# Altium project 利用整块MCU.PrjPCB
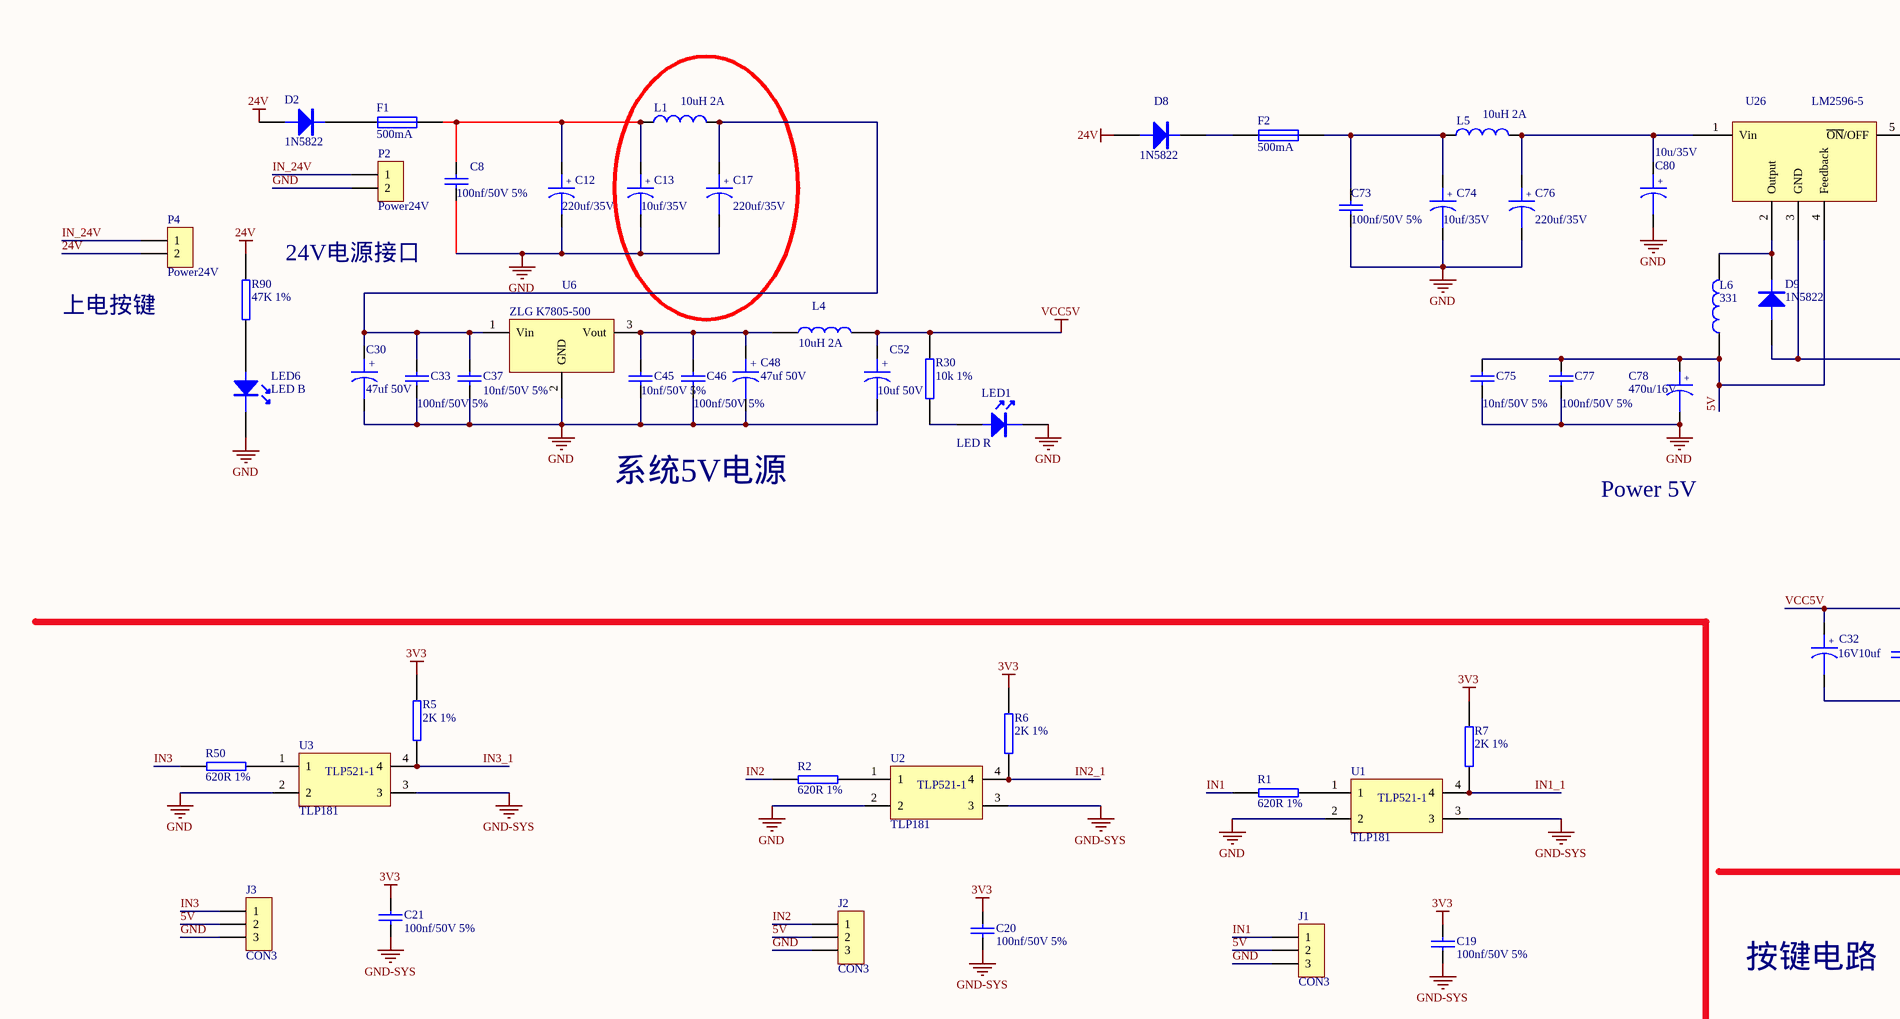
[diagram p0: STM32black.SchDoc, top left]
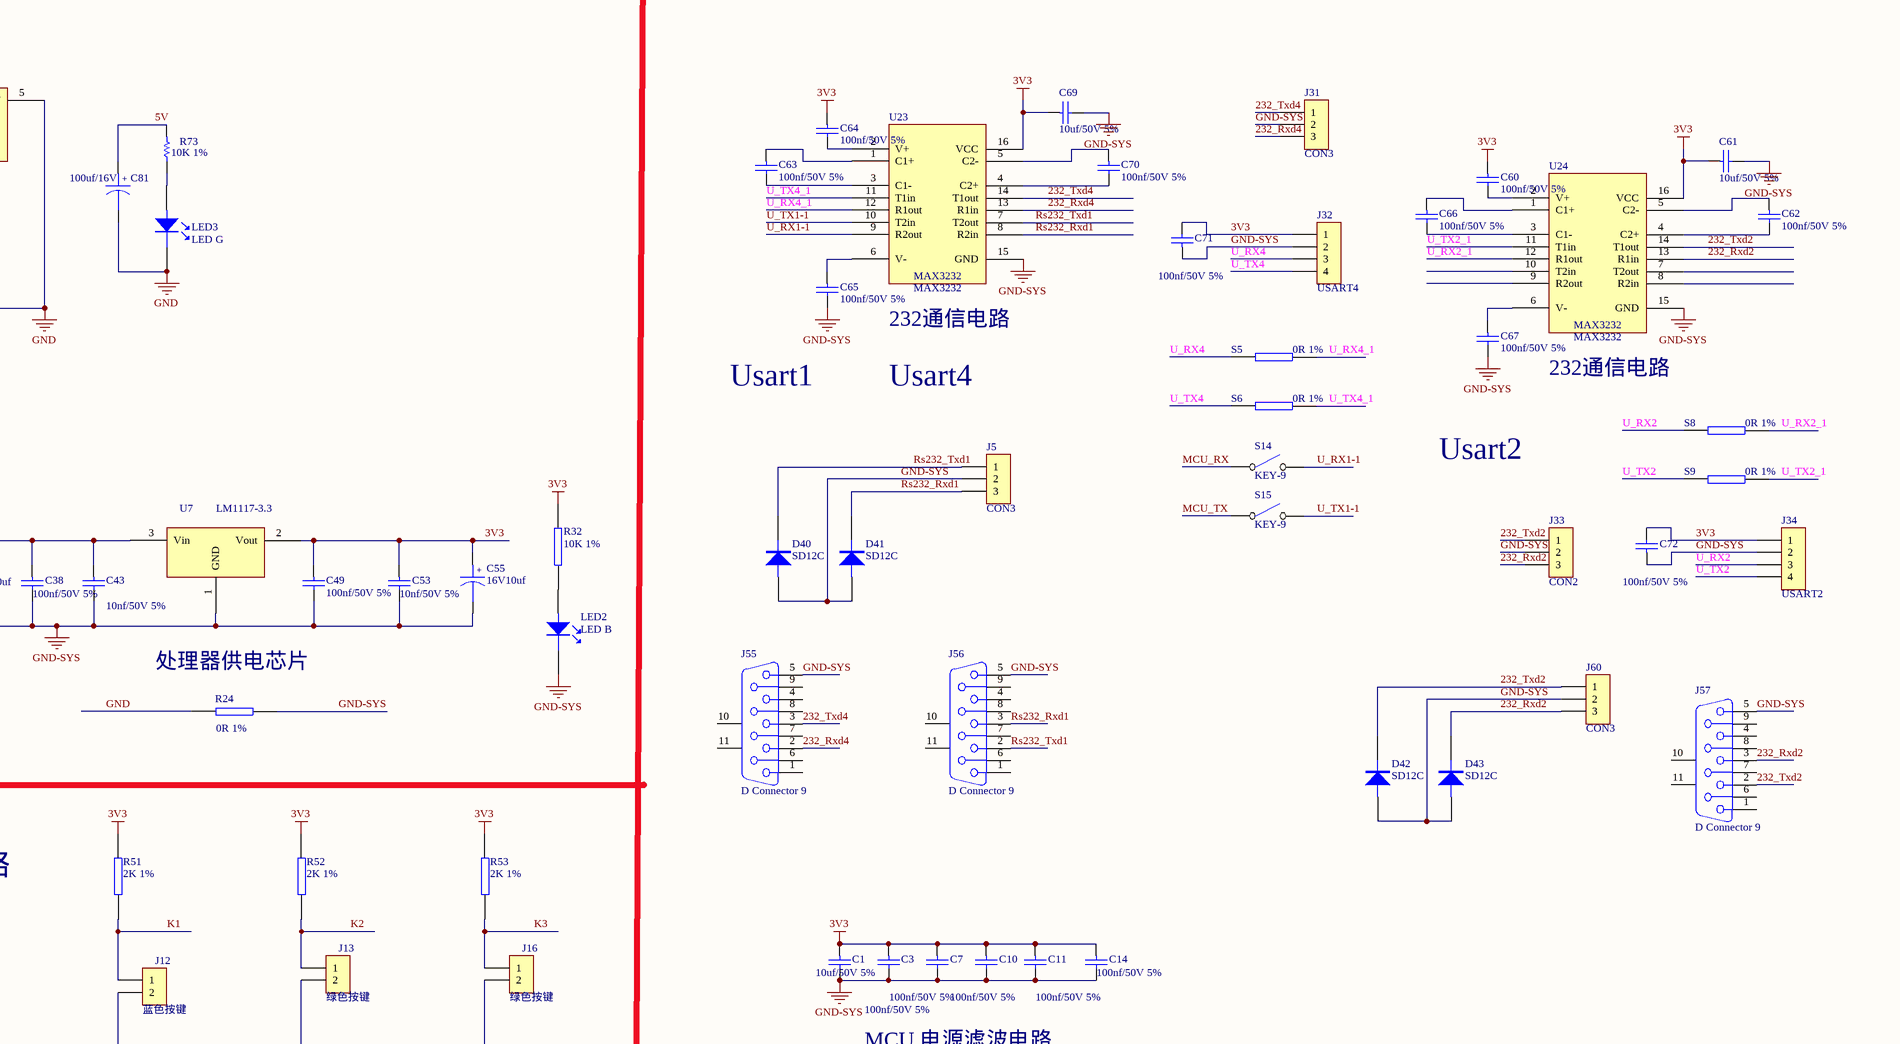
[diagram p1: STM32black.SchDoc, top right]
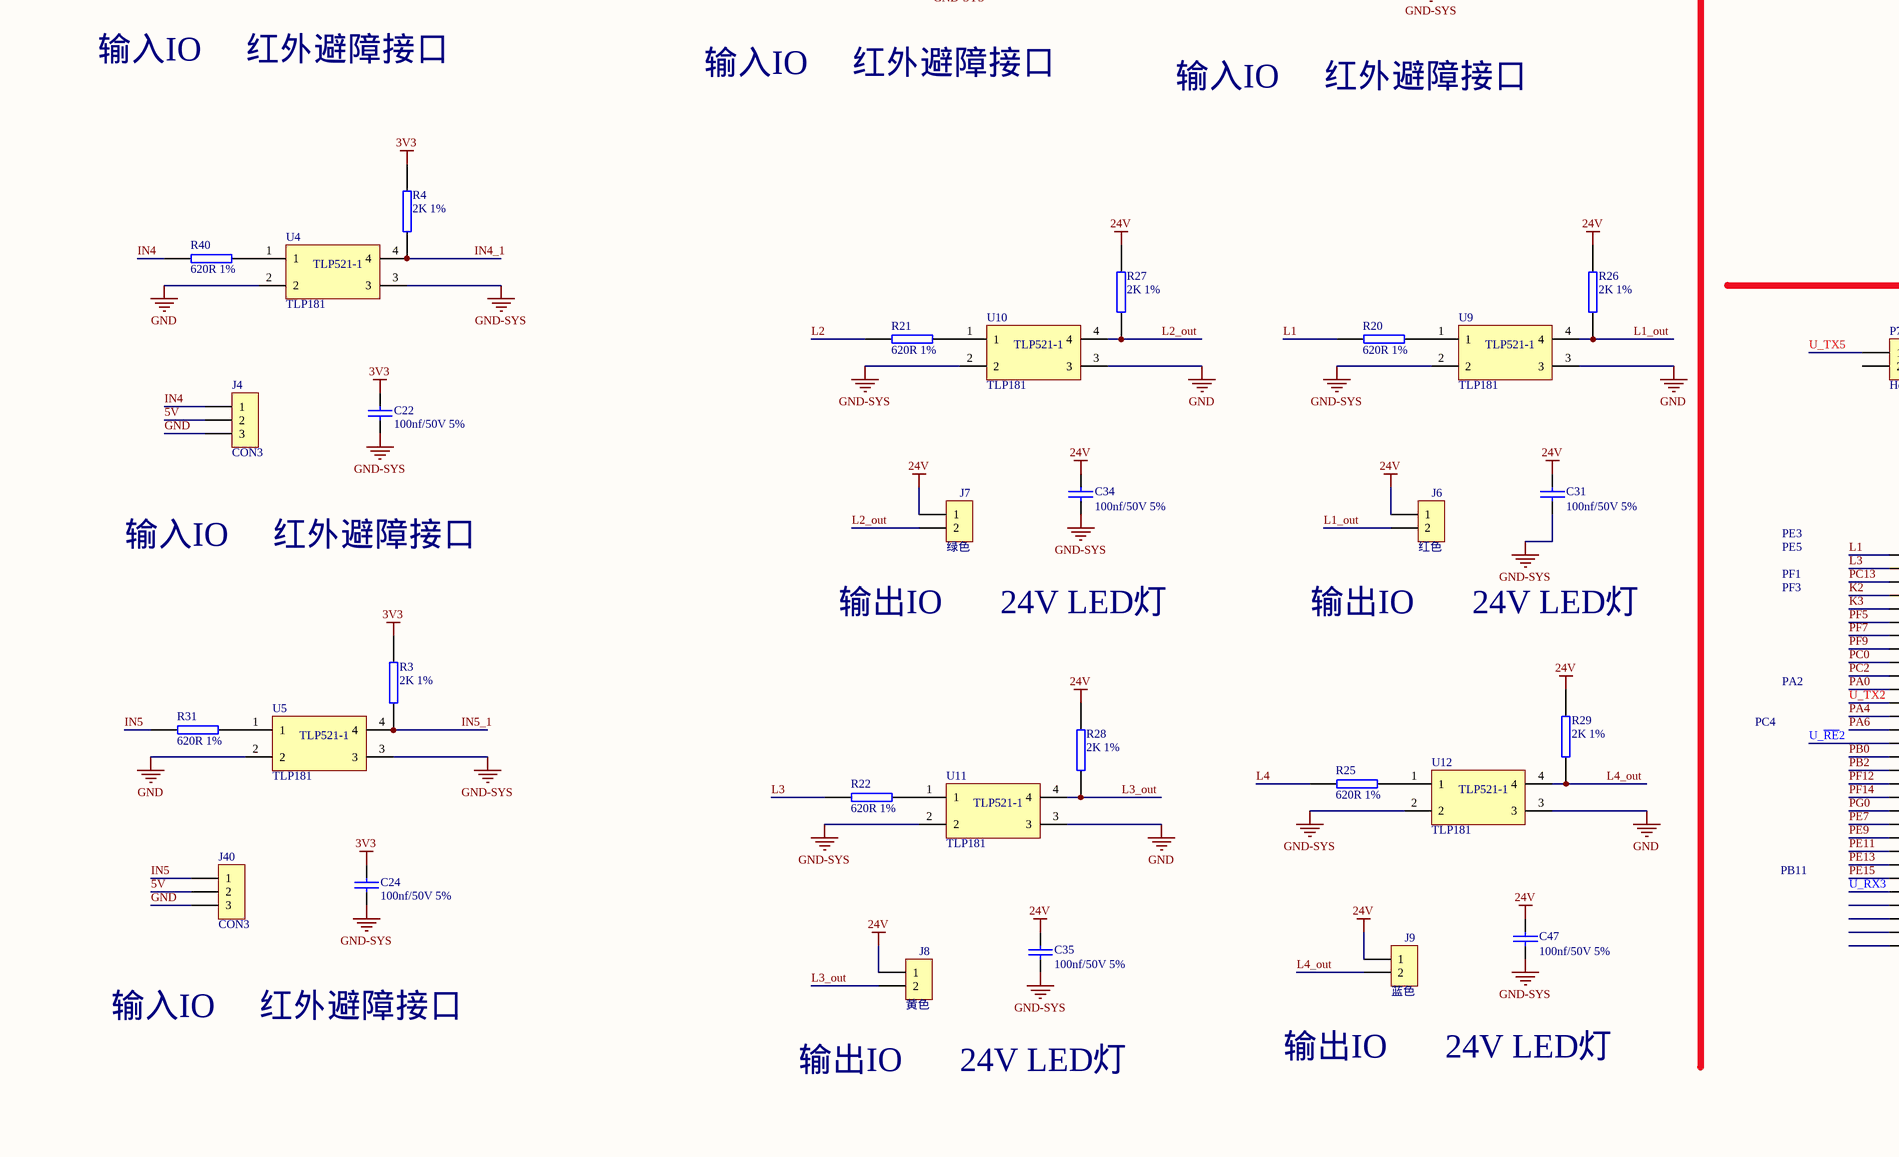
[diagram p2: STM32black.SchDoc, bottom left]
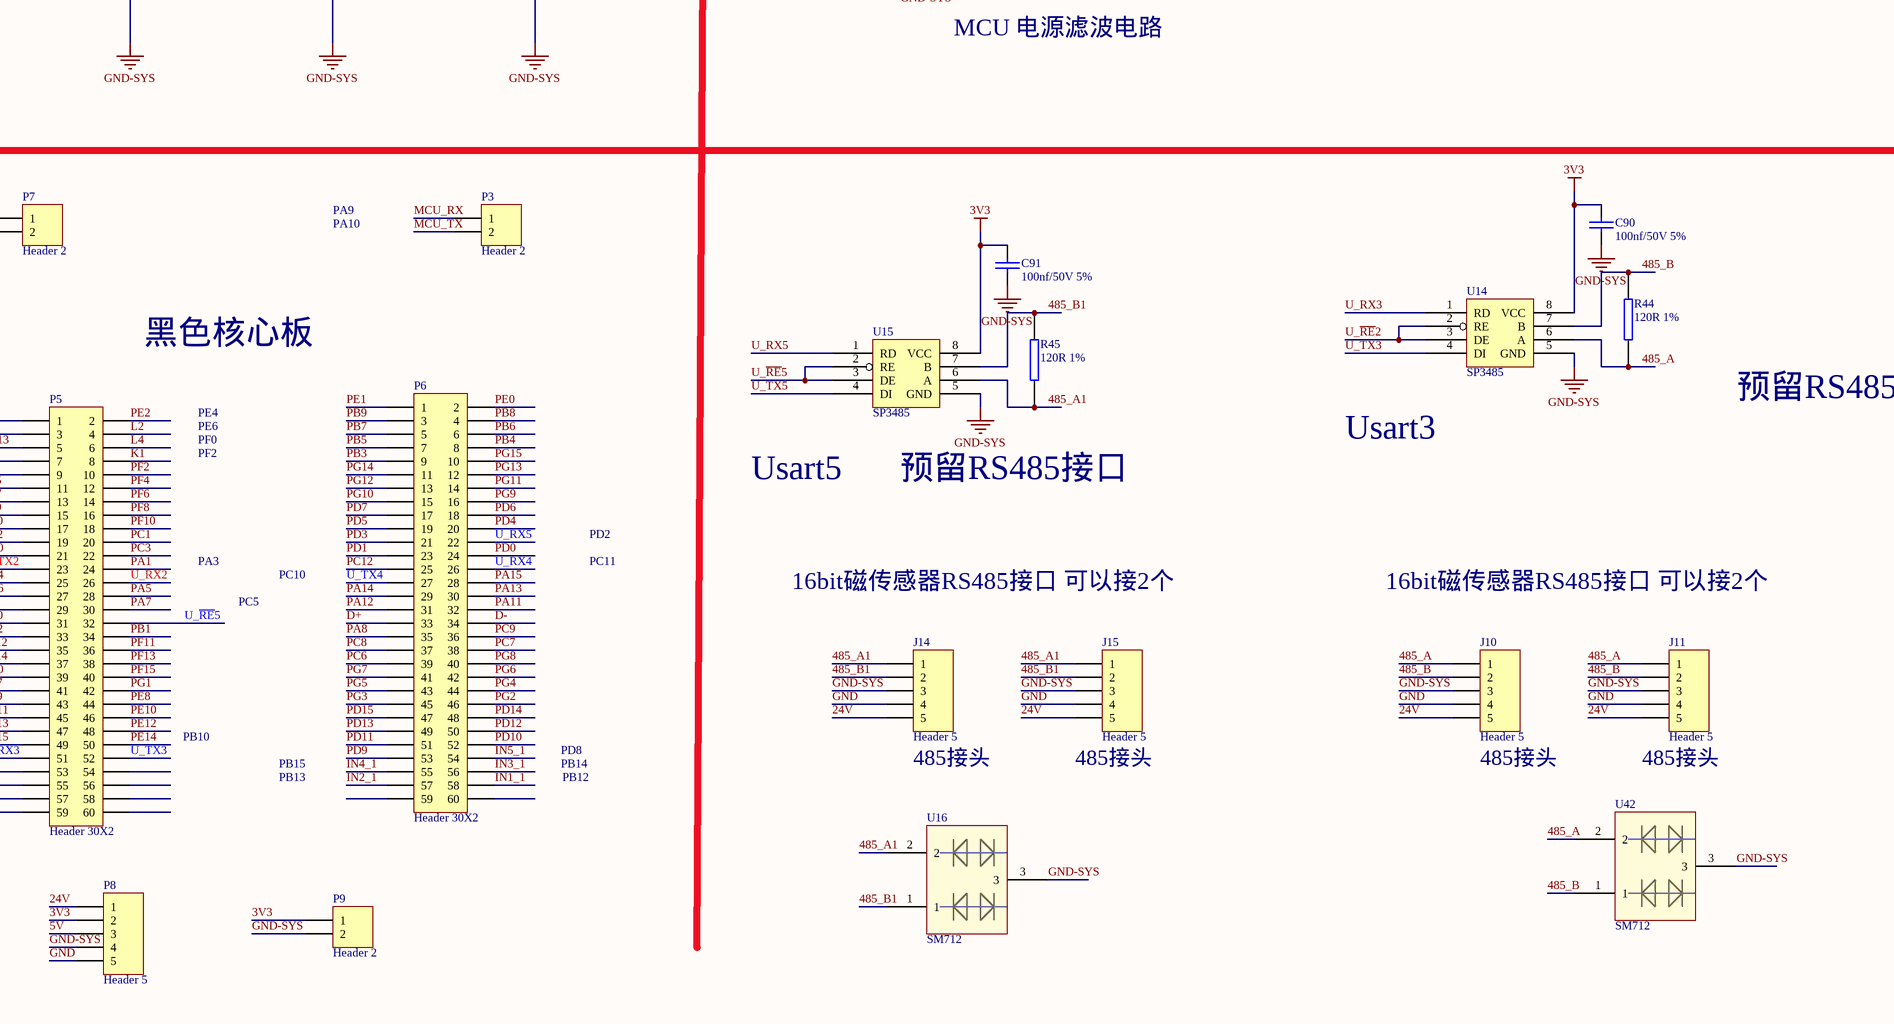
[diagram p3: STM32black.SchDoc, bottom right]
1 sheet, 156 parts. Net scope: global (net labels, ports and power ports of the same name join across sheets).
Board file: 利用整块MCU的投机取巧的PCB板.PcbDoc

## Sheet STM32black.SchDoc
size 762 x 457 mm; SheetNumber: 0; SheetTotal: 0

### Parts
C1  10uf/50V 5%  [0603]
C3  100nf/50V 5%  [0603]
C7  100nf/50V 5%  [0805C]
C8  100nf/50V 5%  [0805C]
C10  100nf/50V 5%  [0805C]
C11  100nf/50V 5%  [0805C]
C12  220uf/35V  [C10-35V330uf]
C13  10uf/35V  [C6.5-35V47uf]
C14  100nf/50V 5%  [0805C]
C17  220uf/35V  [C6.5-35V47uf]
C19  100nf/50V 5%  [0805C]
C20  100nf/50V 5%  [0805C]
C21  100nf/50V 5%  [0805C]
C22  100nf/50V 5%  [0805C]
C24  100nf/50V 5%  [0805C]
C30  47uf 50V  [C6.5-35V47uf]
C31  100nf/50V 5%  [0805C]
C32  16V10uf  [1206-2]
C33  100nf/50V 5%  [0805C]
C34  100nf/50V 5%  [0805C]
C35  100nf/50V 5%  [0805C]
C37  10nf/50V 5%  [0805C]
C38  100nf/50V 5%  [0805C]
C43  10nf/50V 5%  [0805C]
C45  10nf/50V 5%  [0805C]
C46  100nf/50V 5%  [0805C]
C47  100nf/50V 5%  [0805C]
C48  47uf 50V  [C6.5-35V47uf]
C49  100nf/50V 5%  [0805C]
C52  10uf 50V  [C6.5-35V47uf]
C53  10nf/50V 5%  [0805C]
C55  16V10uf  [1206-2]
C60  100nf/50V 5%  [0805C]
C61  10uf/50V 5%  [0805C]
C62  100nf/50V 5%  [0805C]
C63  100nf/50V 5%  [0805C]
C64  100nf/50V 5%  [0805C]
C65  100nf/50V 5%  [0805C]
C66  100nf/50V 5%  [0805C]
C67  100nf/50V 5%  [0805C]
C69  10uf/50V 5%  [0805C]
C70  100nf/50V 5%  [0805C]
C71  100nf/50V 5%  [0805C]
C72  100nf/50V 5%  [0805C]
C73  100nf/50V 5%  [0805C]
C74  10uf/35V  [C6.5-35V47uf]
C75  10nf/50V 5%  [0805C]
C76  220uf/35V  [C6.5-35V47uf]
C77  100nf/50V 5%  [0805C]
C78  470u/16V  [C10-35V330uf]
C80  10u/35V  [C6.5-35V47uf]
C81  100uf/16V  [C6.5-35V47uf]
C90  100nf/50V 5%  [0805C]
C91  100nf/50V 5%  [0805C]
D2  1N5822  [SS34]
D8  1N5822  [SS34]
D9  1N5822  [SS34]
D40  SD12C  [SD12C]
D41  SD12C  [SD12C]
D42  SD12C  [SD12C]
D43  SD12C  [SD12C]
F1  500mA  [1812]
F2  500mA  [1812]
J1  CON3  [CON-3P-3.81]
J2  CON3  [CON-3P-3.81]
J3  CON3  [CON-3P-3.81]
J4  CON3  [CON-3P-3.81]
J5  CON3  [CON-3P-3.81]
J6  红色  [CON-2P-3.81]
J7  绿色  [CON-2P-3.81]
J8  黄色  [CON-2P-3.81]
J9  蓝色  [CON-2P-3.81]
J10  Header 5  [CON-5P-3.81]
J11  Header 5  [CON-5P-3.81]
J12  蓝色按键  [CON-2P-3.81]
J13  绿色按键  [CON-2P-3.81]
J14  Header 5  [CON-5P-3.81]
J15  Header 5  [CON-5P-3.81]
J16  绿色按键  [CON-2P-3.81]
J31  CON3  [CON-3P-3.81]
J32  USART4  [SIP4]
J33  CON2  [CON-3P-3.81]
J34  USART2  [SIP4]
J40  CON3  [CON-3P-3.81]
J55  D Connector 9  [DSUB1.385-2H9]
J56  D Connector 9  [DSUB1.385-2H9]
J57  D Connector 9  [DSUB1.385-2H9]
J60  CON3  [CON-3P-3.81]
L1  value 10uH 2A  [LC-8.2]  (hidden comment: Inductor)
L4  10uH 2A  [LC-8.2]
L5  value 10uH 2A  [LC-8.2]  (hidden comment: Inductor)
L6  331  [LC-10]
LED1  LED R  [0805D]
LED2  LED B  [0805D]
LED3  LED G  [0805D]
LED6  LED B  [0805D]
P2  Power24V  [CON-2P-3.81]
P3  Header 2  [HDR1X2]
P4  Power24V  [CON-2P-3.81]
P5  Header 30X2  [HDR2X30]
P6  Header 30X2  [HDR2X30]
P7  Header 2  [HDR1X2]
P8  Header 5  [HDR1X5]
P9  Header 2  [HDR1X2]
R1  620R 1%  [0805R]
R2  620R 1%  [0805R]
R3  2K 1%  [0805R]
R4  2K 1%  [0805R]
R5  2K 1%  [0805R]
R6  2K 1%  [0805R]
R7  2K 1%  [0805R]
R20  620R 1%  [0805R]
R21  620R 1%  [0805R]
R22  620R 1%  [0805R]
R24  0R 1%  [0805R]
R25  620R 1%  [0805R]
R26  2K 1%  [0805R]
R27  2K 1%  [0805R]
R28  2K 1%  [0805R]
R29  2K 1%  [0805R]
R30  10k 1%  [0805R]
R31  620R 1%  [0805R]
R32  10K 1%  [0805R]
R40  620R 1%  [0805R]
R44  120R 1%  [0805R]
R45  120R 1%  [0805R]
R50  620R 1%  [0805R]
R51  2K 1%  [0805R]
R52  2K 1%  [0805R]
R53  2K 1%  [0805R]
R73  10K 1%  [0805R]
R90  47K 1%  [0805R]
S5  0R 1%  [0805R]
S6  0R 1%  [0805R]
S8  0R 1%  [0805R]
S9  0R 1%  [0805R]
S14  KEY-9  [SIP2]
S15  KEY-9  [SIP2]
U1  TLP181  [TLP-181]
U2  TLP181  [TLP-181]
U3  TLP181  [TLP-181]
U4  TLP181  [TLP-181]
U5  TLP181  [TLP-181]
U6  ZLG K7805-500  [TO-220]
U7  LM1117-3.3  [SOT-223]
U9  TLP181  [TLP-181]
U10  TLP181  [TLP-181]
U11  TLP181  [TLP-181]
U12  TLP181  [TLP-181]
U14  SP3485  [SO-8]
U15  SP3485  [SO-8]
U16  SM712  [SM712]
U23  MAX3232  [SO-16]
U24  MAX3232  [SO-16]
U26  LM2596-5  [TO-263-5]
U42  SM712  [SM712]

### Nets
3V3: C1.1 C3.1 C7.1 C10.1 C11.1 C14.1 C19.2 C20.2 C21.2 C22.2 C24.2 C49.1 C53.1 C55.1 C60.1 C61.1 C64.1 C69.1 C71.2 C72.2 C90.2 C91.2 J32.1 J34.1 P8.2 P9.1 R3.2 R4.2 R5.2 R6.2 R7.2 R32.2 R51.1 R52.1 R53.1 U7.2(Vout) U14.8(VCC) U15.8(VCC) U23.16(VCC) U24.16(VCC)
24V: C31.2 C34.2 C35.2 C47.2 D2.1(A) D8.1(A) J6.1 J7.1 J8.1 J9.1 J10.5 J11.5 J14.5 J15.5 P4.2 P8.1 R26.1 R27.1 R28.1 R29.1 R90.2
GND: C8.2 C12.2 C13.2 C17.2 C30.2 C33.2 C37.2 C45.2 C46.2 C48.2 C52.2 C73.2 C74.2 C75.2 C76.2 C77.2 C78.2 C80.2 C81.2 D9.1(A) J1.3 J2.3 J3.3 J4.3 J10.4 J11.4 J14.4 J15.4 J40.3 LED1.2 LED3.2 LED6.2 P2.2 P8.5 R24.1 U1.2 U2.2 U3.2 U4.2 U5.2 U6.2(GND) U9.3 U10.3 U11.3 U12.3 U26.3(GND) U26.5(~{ON}/OFF)
GND-SYS: C1.2 C3.2 C7.2 C10.2 C11.2 C14.2 C19.1 C20.1 C21.1 C22.1 C24.1 C31.1 C32.2 C34.1 C35.1 C38.2 C43.2 C47.1 C49.2 C53.2 C55.2 C61.2 C65.2 C67.2 C69.2 C71.1 C72.1 C90.1 C91.1 D40.1(A) D41.1(A) D42.1(A) D43.1(A) J5.2 J10.3 J11.3 J12.2 J13.2 J14.3 J15.3 J16.2 J31.2 J32.2 J33.2 J34.2 J55.5 J56.5 J57.5 J60.2 LED2.2 P8.4 P9.2 R24.2 U1.3 U2.3 U3.3 U4.3 U5.3 U7.1(GND) U9.2 U10.2 U11.2 U12.2 U14.5(GND) U15.5(GND) U16.3 U23.15(GND) U24.15(GND) U42.3
VCC5V: C32.1 C38.1 C43.1 C52.1 L4.2 R30.2 U7.3(Vin)
5V: C75.1 C77.1 C78.1 C81.1 J1.2 J2.2 J3.2 J4.2 J40.2 L6.1 P8.3 R73.2 U26.4(Feedback)
232_Rxd2: D43.2(K) J33.3 J57.3 J60.3 U24.13(R1in)
232_Rxd4: J31.3 J55.2 U23.13(R1in)
232_Txd2: D42.2(K) J33.1 J57.2 J60.1 U24.14(T1out)
232_Txd4: J31.1 J55.3 U23.14(T1out)
485_A: J10.1 J11.1 R44.2 U14.6(A) U42.2
485_A1: J14.1 J15.1 R45.2 U15.6(A) U16.2
485_B: J10.2 J11.2 R44.1 U14.7(B) U42.1
485_B1: J14.2 J15.2 R45.1 U15.7(B) U16.1
D+: P6.33
D-: P6.34
IN1: J1.1 R1.2
IN1_1: P6.58 R7.1 U1.4
IN2: J2.1 R2.2
IN2_1: P6.57 R6.1 U2.4
IN3: J3.1 R50.2
IN3_1: P6.56 R5.1 U3.4
IN4: J4.1 R40.2
IN4_1: P6.55 R4.1 U4.4
IN5: J40.1 R31.2
IN5_1: P6.54 R3.1 U5.4
IN_24V: P2.1 P4.1
K1: J12.1 P5.8 R51.2
K2: J13.1 P5.7 R52.2
K3: J16.1 P5.9 R53.2
L1: P5.1 R20.2
L1_out: J6.2 R26.2 U9.4
L2: P5.4 R21.2
L2_out: J7.2 R27.2 U10.4
L3: P5.3 R22.2
L3_out: J8.2 R28.2 U11.4
L4: P5.6 R25.2
L4_out: J9.2 R29.2 U12.4
MCU_RX: P3.1 S14.1(COMMON)
MCU_TX: P3.2 S15.1(COMMON)
PA0: P5.21
PA1: P5.24
PA4: P5.25
PA5: P5.28
PA6: P5.27
PA7: P5.30
PA8: P6.35
PA11: P6.32
PA12: P6.31
PA13: P6.30
PA14: P6.29
PA15: P6.28
PB0: P5.31
PB1: P5.34
PB2: P5.33
PB3: P6.9
PB4: P6.8
PB5: P6.7
PB6: P6.6
PB7: P6.5
PB8: P6.4
PB9: P6.3
PC0: P5.17
PC1: P5.20
PC2: P5.19
PC3: P5.22
PC6: P6.39
PC7: P6.38
PC8: P6.37
PC9: P6.36
PC12: P6.25
PC13: P5.5
PD0: P6.24
PD1: P6.23
PD3: P6.21
PD4: P6.20
PD5: P6.19
PD6: P6.18
PD7: P6.17
PD9: P6.53
PD10: P6.52
PD11: P6.51
PD12: P6.50
PD13: P6.49
PD14: P6.48
PD15: P6.47
PE0: P6.2
PE1: P6.1
PE2: P5.2
PE7: P5.41
PE8: P5.44
PE9: P5.43
PE10: P5.46
PE11: P5.45
PE12: P5.48
PE13: P5.47
PE14: P5.50
PE15: P5.49
PF2: P5.10
PF4: P5.12
PF5: P5.11
PF6: P5.14
PF7: P5.13
PF8: P5.16
PF9: P5.15
PF10: P5.18
PF11: P5.36
PF12: P5.35
PF13: P5.38
PF14: P5.37
PF15: P5.40
PG0: P5.39
PG1: P5.42
PG2: P6.46
PG3: P6.45
PG4: P6.44
PG5: P6.43
PG6: P6.42
PG7: P6.41
PG8: P6.40
PG9: P6.16
PG10: P6.15
PG11: P6.14
PG12: P6.13
PG13: P6.12
PG14: P6.11
PG15: P6.10
Rs232_Rxd1: D41.2(K) J5.3 J56.3 U23.8(R2in)
Rs232_Txd1: D40.2(K) J5.1 J56.2 U23.7(T2out)
U_~{RE}2: P5.29 U14.2(RE) U14.3(DE)
U_~{RE}5: P5.32 U15.2(RE) U15.3(DE)
U_RX1-1: S14.2(NO) U23.9(R2out)
U_RX2: J34.3 P5.26 S8.1
U_RX2_1: S8.2 U24.12(R1out)
U_RX3: P5.51 U14.1(RD)
U_RX4: J32.3 P6.26 S5.1
U_RX4_1: S5.2 U23.12(R1out)
U_RX5: P6.22 U15.1(RD)
U_TX1-1: S15.2(NO) U23.10(T2in)
U_TX2: J34.4 P5.23 S9.1
U_TX2_1: S9.2 U24.11(T1in)
U_TX3: P5.52 U14.4(DI)
U_TX4: J32.4 P6.27 S6.1
U_TX4_1: S6.2 U23.11(T1in)
U_TX5: P7.1 U15.4(DI)
NetC8_1: C8.1 C12.1 C13.1 F1.2 L1.1
NetC17_1: C17.1 C30.1 C33.1 C37.1 L1.2 U6.1(Vin)
NetC45_1: C45.1 C46.1 C48.1 L4.1 U6.3(Vout)
NetC60_2: C60.2 U24.2(V+)
NetC62_1: C62.1 U24.5(C2-)
NetC62_2: C62.2 U24.4(C2+)
NetC63_1: C63.1 U23.1(C1+)
NetC63_2: C63.2 U23.3(C1-)
NetC64_2: C64.2 U23.2(V+)
NetC65_1: C65.1 U23.6(V-)
NetC66_1: C66.1 U24.1(C1+)
NetC66_2: C66.2 U24.3(C1-)
NetC67_1: C67.1 U24.6(V-)
NetC70_1: C70.1 U23.5(C2-)
NetC70_2: C70.2 U23.4(C2+)
NetC73_1: C73.1 C74.1 F2.2 L5.1
NetC76_1: C76.1 C80.1 L5.2 U26.1(Vin)
NetD2_2: D2.2(K) F1.1
NetD8_2: D8.2(K) F2.1
NetD9_2: D9.2(K) L6.2 U26.2(Output)
NetLED1_1: LED1.1 R30.1
NetLED2_1: LED2.1 R32.1
NetLED3_1: LED3.1 R73.1
NetLED6_1: LED6.1 R90.1
NetR1_1: R1.1 U1.1
NetR2_1: R2.1 U2.1
NetR20_1: R20.1 U9.1
NetR21_1: R21.1 U10.1
NetR22_1: R22.1 U11.1
NetR25_1: R25.1 U12.1
NetR31_1: R31.1 U5.1
NetR40_1: R40.1 U4.1
NetR50_1: R50.1 U3.1

Not connected (* = marked no-connect by the designer): J55 1 4 6 7 8 9 10(MH1) 11(MH2); J56 1 4 6 7 8 9 10(MH1) 11(MH2); J57 1 4 6 7 8 9 10(MH1) 11(MH2); P5 53 54 55 56 57 58 59 60; P6 59 60; P7 2; U24 7(T2out) 8(R2in) 9(R2out) 10(T2in)

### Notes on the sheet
- 上电按键
- 24V电源接口
- 232通信电路
- Usart1
- Usart4
- 系统5V电源
- Power 5V
- Usart2
- (near R24) 处理器供电芯片
- 按键电路
- 输入IO
- 红外避障接口
- MCU 电源滤波电路
- PA9
- PA10
- 黑色核心板
- PE3
- PE5
- PF1
- PF3
- PE4
- PE6
- PF0
- PF2
- Usart3
- 预留RS485接口
- 输出IO
- 24V LED灯
- Usart5
- PC4
- PA2
- PA3
- PC10
- PC11
- PD2
- 16bit磁传感器RS485接口 可以接2个
- PC5
- PB11
- PB10
- PB13
- PB15
- PB14
- PD8
- PB12
- (near J14) 485接头
- (near J15) 485接头
- (near J10) 485接头
- (near J11) 485接头

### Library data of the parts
C1 C3 C7 C8 C10 C11 C14 C19-C22 C24 C31 C33-C35 C37 C38 C43 C45-C47 C49 C53 C60-C67 C69-C73 C75 C77 C90 C91 = CAP: Capacitor
C12 C13 C17 C30 C48 C52 C74 C76 C78 C80 C81 = CAPACITOR POL: Capacitor
C32 C55 = CAP+
D2 D8 D9 D40-D43 = DIODE
F1 F2 = Fuse 1: Fuse
J1-J5 J31 J33 J40 J60 = CON3: Connector
J6-J9 J12 J13 J16 P2 P4 = CON2: Connector
J10 J11 J14 J15 P8 = Header 5: Header, 5-Pin
J32 J34 = CON4: Connector
J55-J57 = D Connector 9: Receptacle Assembly, 9 Position, Right Angle; PackageDocument: O; Positions: 9
L1 L5 = Inductor: Code_IEC: 1005
L4 = INDUCTOR1
L6 = INDUCTOR
LED1-LED3 LED6 = LED
P3 P7 P9 = Header 2: Header, 2-Pin
P5 P6 = Header 30X2: Header, 30-Pin, Dual row
R1-R7 R20-R22 R24-R32 R40 R44 R45 R50-R53 R90 = RES2
R73 = Res1: Resistor
S5 S6 S8 S9 = RES
S14 S15 = KEY-2
U1-U5 U9-U12 = TLP521-1
U6 = VOLTREG
U7 = LM1117
U14 U15 = MAX485
U26 = LM2596-5.0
